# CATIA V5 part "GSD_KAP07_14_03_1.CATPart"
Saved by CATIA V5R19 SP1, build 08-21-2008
Part number: GSD_KAP07_14_03
Definition: Beispielmodell für die Funktion Eckenverrundung / EdgeFillet - Ecken verrunden.
Description: CATIA V5 Flächenmodellierung  Copyright (c) 2009 Maik Hertha IT Consultants
Bounding box of the stored display mesh (mm): x -56.661 to 55.861, y -41.128 to 65.964, z -10 to 30
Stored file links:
  \GSD_BUCH_UEBUNG\GSD_KAP07_14_03_1.CATPart
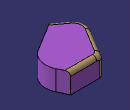
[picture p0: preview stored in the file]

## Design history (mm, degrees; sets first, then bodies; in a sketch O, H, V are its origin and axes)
AxisSystem1 "Absolute Axis System": origin (0, 0, 0), X (1, 0, 0), Y (0, 1, 0), Z (0, 0, 1)
Set1 "Edge Support"
  Plane1: type Equation, A 0, B 0, C 1, Length -10
  Point1: type OnPlane, Support Plane1, Direction (1, 0, 0), H 10, V 10
  Sketch1 on Plane1, origin (10, 10, -10), H (0, 1, 0), V (-1, 0, 0)
    line L1 (-51.1279, 33.3631) -> (-33.587, 56.515)
    arc A1 centre (-13.1715, 41.0472) radius 25.6134 from (-33.587, 56.515) to (0.0896, 62.9604) cw
    line L2 (0.0896, 62.9604) -> (55.9639, 29.1473)
    line L3 (55.9639, 29.1473) -> (55.9639, -32.6844)
    line L4 (55.9639, -32.6844) -> (35.6076, -42.197)
    arc A2 centre (19.1105, -6.8942) radius 38.9672 from (35.6076, -42.197) to (-11.5309, -30.968) cw
    line L5 (-11.5309, -30.968) -> (-51.1279, 33.3631)
    curve C1
    construction line L6 (-0.9087, -48.1015) -> (-25.9518, -8.5836)
    angle L5 L6 = 0.75
    tangency: A1 L1, L2 A1, A2 L4, L6 A2
    vertical: L3 V
  Split1: ToCut Plane1, Cutting Sketch1.C1
  Extrude1: Lim1 40, Lim2 0, Element1 Split1, Direction Plane1
Set2 "Edge 1"
  DatumSurface1: linked copy from another document
  Fillet1: radius 8, on edge [face of DatumSurface1 | face of DatumSurface1] (x3)
Body1 (main body)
